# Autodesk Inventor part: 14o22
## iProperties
Created: 2005-05
Part Number: 14o22
Document SubType Name: Modeling
Designer: rfheme
Manufacturer: Standard
Standards Organization: Custom
Author: rfheme
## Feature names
1. Extrusion1
2. Chamfer1
3. Extrusion2
4. Fillet1
5. Hole1
6. Extrusion4
7. Extrusion5
8. Extrusion6
9. Fillet2
10. Extrusion7
11. Fillet3
12. Extrusion8
13. Chamfer2
14. Extrusion9
15. Rectangular Pattern1
16. Mirror2
